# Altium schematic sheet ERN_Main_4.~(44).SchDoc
size A; SheetNumber: 4; SheetTotal: 4; SPICEModelCacheELVNKBHK: <root> / <DocumentId>ELVNKBHK</DocumentId> / <CacheFrame Number="0"> / <Model Name="led2" Kind="MDL"> / <Text>*Typ RED,GREEN,YELLOW,AMBER GaAs LED: Vf=2.1V Vr=4V If=40mA trr=3uS / *LED Pinout: 1=A, 2=K / .MODEL LED2 D (IS=93.1P RS=42M N=4.61 BV=4 IBV=10U / + CJO=2.97P VJ=.75 M=.333 TT=4.32U)</Text> / </Model> / <Model Name="1n5400" Kind="MDL"> / <Text>*1N5400 MCE / * 50V 3A Si Rectifier pkg:DO-201 1,2 / .MODEL 1N5400 D(IS=2.68E-12 RS=0.00977 N=1.17 TT=1.44E-5 CJO=1.24E-10 / + VJ=0.6 M=0.333 BV=66.6 IBV=1E-5 )</Text> / </Model> / </CacheFrame> / </root>
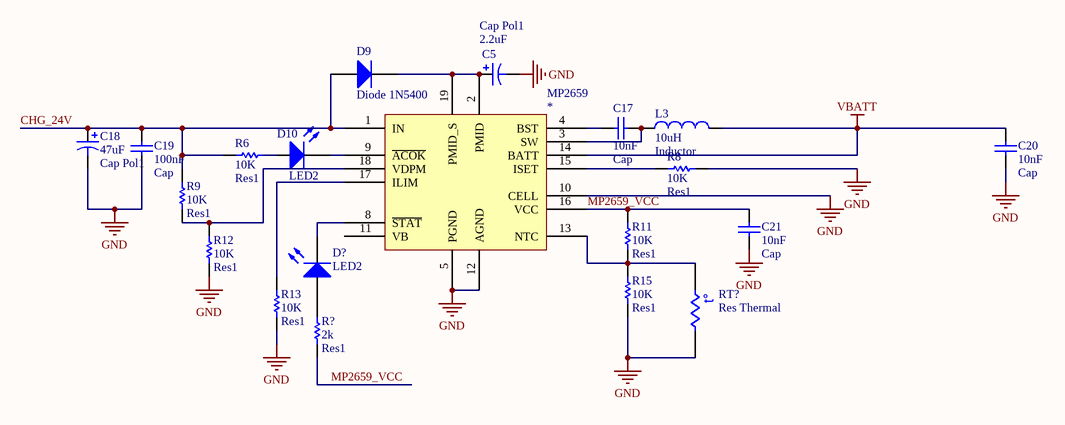
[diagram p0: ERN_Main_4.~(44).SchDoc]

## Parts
*  MP2659
C5  Cap Pol1  value 2.2uF  [RB7.6-15]
C17  Cap  value 10nF  [RAD-0.3]
C18  Cap Pol1  value 47uF  [RB7.6-15]
C19  Cap  value 100nF  [RAD-0.3]
C20  Cap  value 10nF  [RAD-0.3]
C21  Cap  value 10nF  [RAD-0.3]
D9  Diode 1N5400  [DO-201AD]
D10  LED2  [3.2X1.6X1.1]
D?  LED2  [3.2X1.6X1.1]
L3  Inductor  value 10uH  [0402-A]
R6  Res1  value 10K  [AXIAL-0.3]
R8  Res1  value 10K  [AXIAL-0.3]
R9  Res1  value 10K  [AXIAL-0.3]
R11  Res1  value 10K  [AXIAL-0.3]
R12  Res1  value 10K  [AXIAL-0.3]
R13  Res1  value 10K  [AXIAL-0.3]
R15  Res1  value 10K  [AXIAL-0.3]
R?  Res1  value 2k  [AXIAL-0.3]
RT?  Res Thermal  [6-0805_N]

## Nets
GND: *.5(PGND) *.10(CELL) *.12(AGND) C5.2 C18.2 C19.1 C20.2 C21.2 R8.2 R12.2 R13.2 R15.1 RT?.2
VBATT: *.14(BATT) C20.1 L3.2
CHG_24V: *.1(IN) C18.1 C19.2 D9.1(A) R6.2 R9.1
MP2659_VCC: *.16(VCC) C21.1 R11.2 R?.2
Net*_2: *.2(PMID) *.19(PMID_S) C5.1 D9.2(K)
Net*_3: *.3(SW) C17.1 L3.1
Net*_4: *.4(BST) C17.2
Net*_8: *.8(~{STAT}) D?.2(K)
Net*_9: *.9(~{ACOK}) D10.2(K)
Net*_13: *.13(NTC) R11.1 R15.2 RT?.1
Net*_15: *.15(ISET) R8.1
Net*_17: *.17(ILIM) R13.1
Net*_18: *.18(VDPM) R9.2 R12.1
NetD10_1: D10.1(A) R6.1
NetD?_1: D?.1(A) R?.1

Not connected (* = marked no-connect by the designer): * 11(VB)

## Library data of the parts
* = MP2659: 3S-6S Standalone Switching Charger
C5 C18 = Cap Pol1: Polarized Capacitor (Radial)
C17 C19-C21 = Cap: Capacitor
D9 = Diode 1N5400: 3 Amp General Purpose Rectifier
D10 D? = LED2: Typical RED, GREEN, YELLOW, AMBER GaAs LED
L3 = Inductor: Code_IEC: 1005
R6 R8 R9 R11-R13 R15 R? = Res1: Resistor
RT? = Res Thermal: Thermistor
